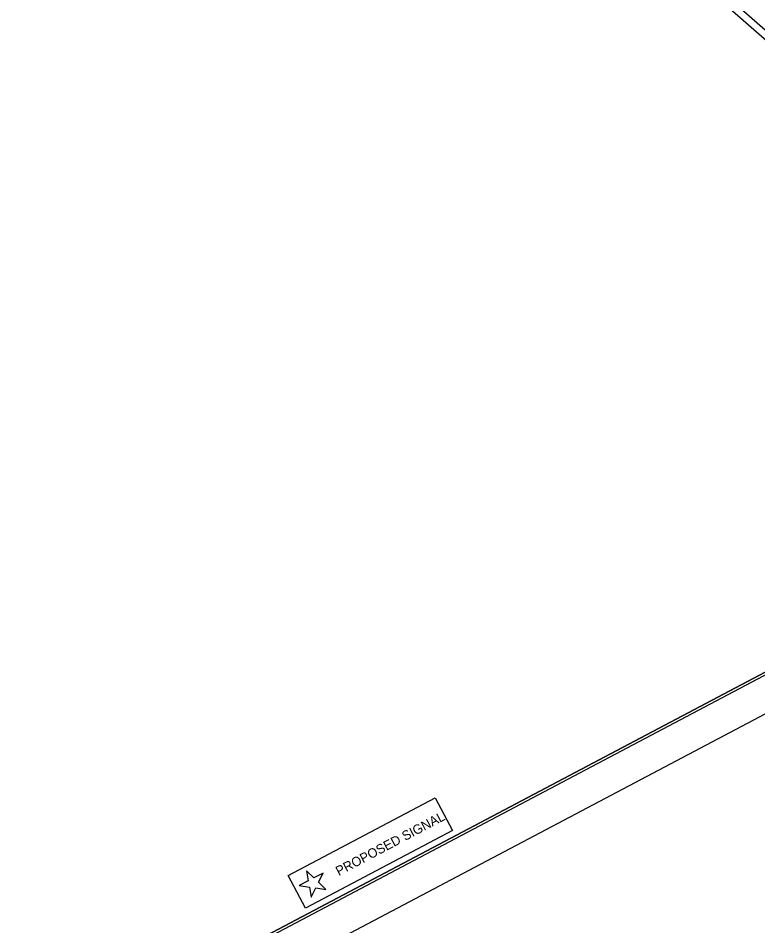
# Model space of a CAD drawing. Extents: x 1487051 to 1489241, y 497582 to 499399.
# Drawn here: x 1488337 to 1488789, y 498103 to 498657 of the extents above; entities that cross this region are included whole.
import ezdxf

# ---------------------------------------------------------------- set-up
doc = ezdxf.new("R2010")
doc.units = 0
for name, color, linetype in [('Exist DTM Regular Point Cogo Elevation', 7, 'Continuous'), ('Exist Other Culture Sign Post Cogo Comment', 7, 'Continuous'), ('Exist Other Culture Sign Post Cogo Elevation', 7, 'Continuous'), ('Exist Other Culture Sign Post Cogo Number', 7, 'Continuous'), ('Exist Roads EOP Cogo Point CELL', 7, 'Continuous'), ('Exist Structure Minor Pipes RCP 15 Inch Cogo Comment', 7, 'Continuous'), ('Exist Vegetation Woods Line Cogo Elevation', 7, 'Continuous')]:
    doc.layers.add(name, color=color, linetype=linetype)

msp = doc.modelspace()

# ---------------------------------------------------------------- linework, layer by layer
at = {"layer": 'Exist DTM Regular Point Cogo Elevation'}
for points in [[(1487208.66, 498608.09), (1488222.07, 499143.23), (1488965.37, 498493.68), (1489025.39, 498380), (1487698.94, 497679.61)], [(1487208.66, 498608.09), (1488222.07, 499143.23), (1488965.37, 498493.68), (1489025.39, 498380), (1487698.94, 497679.61)], [(1487214.01, 498609.18), (1488227.42, 499144.32), (1488970.72, 498494.78), (1489030.74, 498381.1), (1487704.3, 497680.71)]]:
    msp.add_lwpolyline(points, close=True, dxfattribs=at)
at = {"layer": 'Exist Other Culture Sign Post Cogo Comment'}
msp.add_lwpolyline([(1488264.23, 499106.38), (1488223.12, 499143.79), (1487208.65, 498608.11), (1487698.94, 497679.61), (1489025.4, 498380.01), (1488871.95, 498670.61), (1488744.3, 498686.86)], close=True, dxfattribs=at)
at = {"layer": 'Exist Other Culture Sign Post Cogo Elevation'}
msp.add_lwpolyline([(1488514.56, 498130.18), (1488509.03, 498127.26), (1488515.22, 498126.37), (1488516.29, 498120.19), (1488519.06, 498125.82), (1488525.26, 498124.93), (1488520.77, 498129.29), (1488523.53, 498134.91), (1488517.99, 498131.99), (1488513.49, 498136.36), (1488514.56, 498130.18)], dxfattribs=at)
at = {"layer": 'Exist Roads EOP Cogo Point CELL'}
msp.add_lwpolyline([(1487562.23, 497581.96), (1489050.94, 498368.04), (1488539.66, 499336.34), (1487050.94, 498550.27)], close=True, dxfattribs=at)
at = {"layer": 'Exist Structure Minor Pipes RCP 15 Inch Cogo Comment'}
for points in [[(1488535.14, 499308.53), (1487208.67, 498608.12), (1487698.94, 497679.61), (1489025.4, 498380.01)], [(1487698.94, 497679.61), (1487208.66, 498608.09), (1488358.21, 499215.12), (1488375.74, 499181.9), (1488552.62, 499275.32), (1489025.4, 498380.01)]]:
    msp.add_lwpolyline(points, close=True, dxfattribs=at)
at = {"layer": 'Exist Vegetation Woods Line Cogo Elevation'}
msp.add_lwpolyline([(1488502.21, 498133.44), (1488591.98, 498180.84), (1488602.55, 498160.84), (1488512.77, 498113.44)], close=True, dxfattribs=at)

# ---------------------------------------------------------------- texts
at = {"layer": 'Exist Other Culture Sign Post Cogo Number'}
msp.add_text('PROPOSED SIGNAL', height=5.75, rotation=27.8351, dxfattribs=at).set_placement((1488533.17, 498133.07))

doc.saveas('drawing.dxf')
